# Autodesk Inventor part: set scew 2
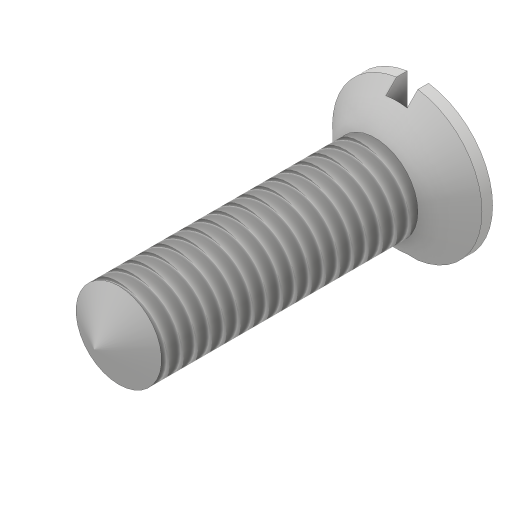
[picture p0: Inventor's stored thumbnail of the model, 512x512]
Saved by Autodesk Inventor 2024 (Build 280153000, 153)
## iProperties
Created: 2016-06
Part Number: set scew 2
Material: Generic
Document SubType Name: Modeling
Designer: CADCIM
Density: 1 g/cm^3
Appearance: Default
Mass: 0.690766 g
Surface Area: 5.88069 cm^2
Volume: 0.690766 cm^3
Author: CADCIM
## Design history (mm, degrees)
sketch "Sketch1"
  geometry: C1 r 3 at (0, 0); 1 further point
  constraints: 1 centre point, 1 coincident
  dimensions: "d0" = 6 diameter of C1
extrude "Extrusion1" new body sketch "Sketch1" distance "d1" = 18; taper "d2" = 0 deg
revolve "Revolution1" stored, may be unused: angle "d7" = 90 deg
sketch "Sketch3"
  geometry: C1 r 5.25 at (0, 0); 1 further point
  constraints: 1 centre point, 1 coincident
  dimensions: "d8" = 10.5 diameter of C1
extrude "Extrusion2" sketch "Sketch3" distance "d9" = 26.75; taper "d10" = 0 deg
sketch "Sketch4"
  geometry: L1 (-0.75, 8.347)-(0.75, 8.347); L2 (0.75, 8.347)-(0.75, -8.125); L3 (0.75, -8.125)-(-0.75, -8.125); L4 (-0.75, -8.125)-(-0.75, 8.347); L5 (0, 0)-(0, 6.165)
  constraints: 10 end point, 3 parallel, 1 horizontal, 1 perpendicular, 1 other
  dimensions: "d11" = 1.5 distance of L1.start L1.end
extrude "Extrusion3" cut sketch "Sketch4" distance "d12" = 1.5; taper "d13" = 0 deg
thread "Thread2" dims "d19" = 10, "d20" = 0
revolve "Revolution3" stored, may be unused: angle "d23" = 90 deg
body "Solid1"
sketch "Sketch5"
  geometry: L1 (0, 0)-(0, 3); L2 (0, 3)-(-1.732, 0); L3 (-1.732, 0)-(0, 0); L4 (0, 3)-(0, -3) reference; 1 further point
  constraints: 6 end point, 2 midpoint, 1 perpendicular, 1 point on line, 1 vertical
  dimensions: "d21" = 60 deg angle of L2 L3; "d22" = 3 distance of L1.start L1.end
sketch "Sketch2"
  geometry: L1 (18, -3)-(18, 3) reference; L2 (18, 0)-(18, -3); L3 (18, -3)-(21, -6); L4 (21, -6)-(21, 0); L5 (21, 0)-(18, 0); 1 further point
  constraints: 8 end point, 2 vertical, 1 midpoint, 1 perpendicular
  dimensions: "d4" = 3 distance of L2.start L2.end; "d5" = 6 distance of L4.end L3.end; "d6" = 3 distance from line of L1.start L4
